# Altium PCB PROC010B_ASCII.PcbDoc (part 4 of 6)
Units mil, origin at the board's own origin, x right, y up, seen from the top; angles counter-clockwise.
Board outline 3180 x 2565 mil, 6 copper layers (TOP, L2, L3, L4, L5, BOTTOM), stack 55.54 mil thick; 362 components, 264 nets, 1248 pads, 1144 vias.
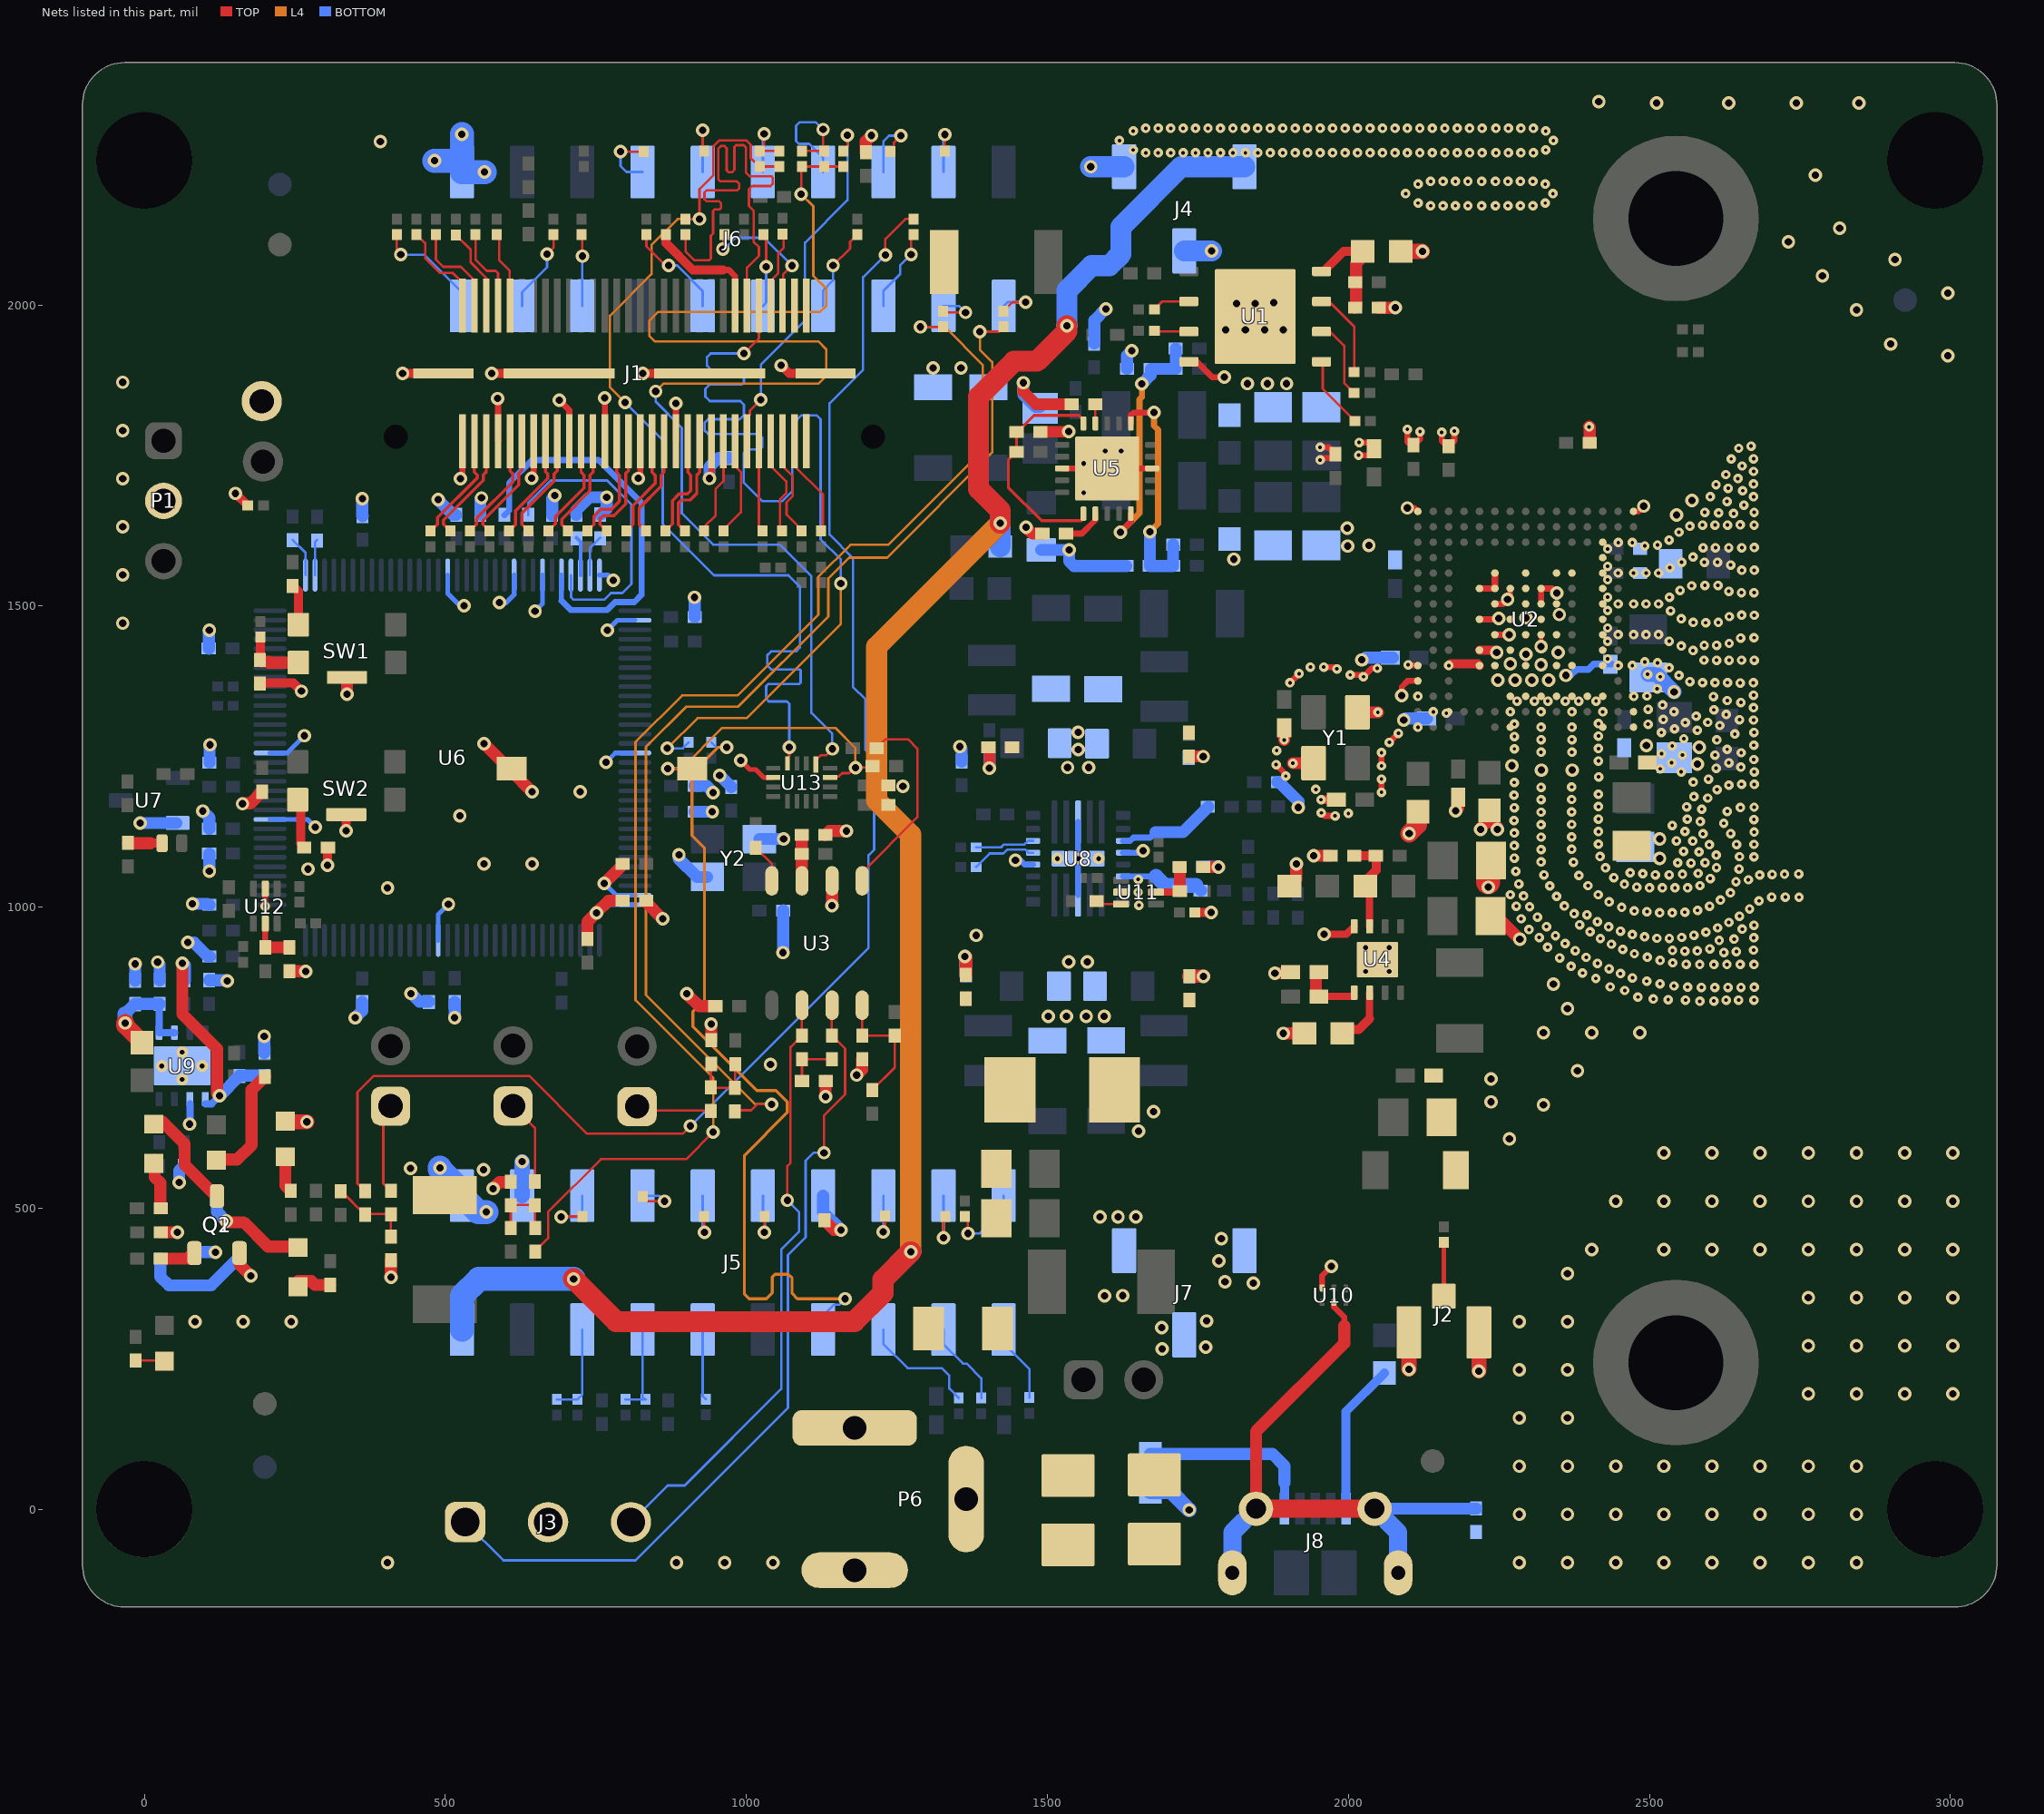
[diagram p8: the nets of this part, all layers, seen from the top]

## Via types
v1: diameter 22.4, hole 12.2, TOP to BOTTOM, tented both sides, 621 vias
v2: diameter 15.74, hole 5.9, TOP to L2, tented top, 508 vias
v3: diameter 19.68, hole 7.87, TOP to BOTTOM, tented top, 7 vias
v4: diameter 19.68, hole 7.87, TOP to BOTTOM, 4 vias
v5: diameter 19.68, hole 7.87, TOP to BOTTOM, tented both sides, 3 vias
v6: diameter 19.68, hole 7.87, TOP to BOTTOM, tented bottom, 1 vias

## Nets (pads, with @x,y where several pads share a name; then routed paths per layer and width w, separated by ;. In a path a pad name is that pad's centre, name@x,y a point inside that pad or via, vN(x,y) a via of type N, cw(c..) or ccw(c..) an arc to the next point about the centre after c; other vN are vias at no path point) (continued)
GND: C1.1 C2.1 C3.2 C4.2 C5.2 C6.2 C7.2 C8.2 C9.2 C10.2 C11.1 C12.2 C13.2 C14.2 C15.1 C16.1 C17.2 C19.2 C20.1 C21.2 C22.2 C23.2 C24.1 C25.2 C26.2 C27.2 C29.1 C30.1 C31.1 C32.1 C33.1 C34.1 C35.1 C36.1 C37.1 C38.1 C39.2 C40.1 C41.1 C42.1 C43.1 C44.1 C45.2 C47.2 C48.2 C49.1 C50.1 C51.2 C52.2 C53.2 C54.1 C55.1 C56.2 C57.2 C58.2 C59.1 C60.1 C61.1 C62.1 C63.1 C64.1 C65.2 C66.1 C67.1 C68.1 C69.1 C70.1 C71.1 C72.1 C73.1 C74.1 C75.1 C76.1 C77.1 C79.1 C80.1 C81.1 C82.1 C83.2 C84.1 C85.2 C86.1 C87.1 C88.1 C89.1 C90.1 C91.1 D3.2 DS2.2 J1.18 J1.24 J1.30 J1.36 J1.42 J1.48 J1.54 J1.60 J1.MP1 J1.MP2 J1.MP3 J1.MP4 J2.2 J2.3 J3.2 J4.1 J4.2 J5.4 J6.2 J7.1 J7.2 P1.2 P6.2 P6.3 Q1.2 Q2.2 R13.1 R47.2 R73.1 R79.1 R81.1 R83.1 R86.2 R88.1 R96.1 R110.1 R114.1 R119.1 R121.1 R123.2 R126.2 R132.1 R138.1 R139.1 R153.1 R157.1 R158.1 R174.1 R175.1 R181.2 R194.1 R195.2 R196.1 S1.1 SW1.5 SW2.5 TP1.1 U1.4 U1.9 U2.A1 U2.A3 U2.A5 U2.A7 U2.A9 U2.A15 U2.B1 U2.B3 U2.B5 U2.B7 U2.B9 U2.B13 U2.B14 U2.C1 U2.C3 U2.C4 U2.C5 U2.C6 U2.C7 U2.C8 U2.C9 U2.C15 U2.D15 U2.E1 U2.E2 U2.E3 U2.E5 U2.E6 U2.E8 U2.E10 U2.E11 U2.E13 U2.E15 U2.F3 U2.F9 U2.F11 U2.G1 U2.G2 U2.G3 U2.G6 U2.G7 U2.G8 U2.G10 U2.H3 U2.H7 U2.H9 U2.H11 U2.J1 U2.J2 U2.J3 U2.J6 U2.J7 U2.J8 U2.J10 U2.K3 U2.K7 U2.K8 U2.K9 U2.K10 U2.K11 U2.L1 U2.L2 U2.L3 U2.L5 U2.L6 U2.L8 U2.L10 U2.M3 U2.N1 U2.N2 U2.N3 U2.R1 U2.R15 U3.2 U4.4 U4.9 U5.3 U5.13 U5.21@1599.35,1728.32 U6.10 U6.17 U6.48 U6.55 U6.58 U6.64 U6.66 U6.80 U6.114 U7.2 U8.4 U8.11 U8.17 U8.24 U8.27 U9.6 U9.9@62.83,736.32 U10.3 U11.2 U12.2 U13.6 Y1.2 Y1.4 Y2.2 Y2.4 | length 6887.4
  TOP w7: U2.J7@2318.89,1503.49 U2.J7@2320.14,1503.49 U2.J7@2320.61,1503.49 ; U2.G7@2320.14,1452.31 U2.G7@2320.14,1452.31 v1@2320.14,1432.71
  TOP w7.8: v1(990.51,1243.73) 1005.75,1228.49 1015.79,1228.49 1029.2,1215.08 U13.6@1044.61,1215.08
  TOP w9: v1(2264.45,1510.8) 2268.96,1515.31 U2.K9@2268.96,1529.08
  TOP w9.45: U5.3@1524.55,1728.32 U5.13@1674.15,1728.32
  TOP w10: v2(200.81,1001.56) U12.2@200.82,1030.67 ; v1(524.98,1711.53) 528.62,1715.17 J1.60@528.62,1773.27 ; v1(587,1844.5) 587.67,1844.5 J1.54@587.67,1773.27 ; v1(643.53,1711.97) 646.73,1715.17 J1.48@646.73,1773.27 ; v1(689.11,1841.85) 705.78,1825.18 J1.42@705.78,1773.46 J1.42@705.78,1773.27 ; J1.36@764.84,1773.27 v1(764.84,1845.5) ; v1(820.61,1711.89) 823.89,1715.17 J1.30@823.89,1773.27 ; J1.24@882.95,1773.46 v1(882.95,1836.43) ; v1(938.67,1711.84) 942,1715.17 J1.18@942,1773.27 ; U1.4@1734.99,1905.68 1748.12,1905.68 1773.8,1880 v1(1794,1880) ; v2(1880,1236.5) 1896,1220.5 v2(1896,1217.5) ; v2(1903,1372.5) v2(1918,1387.5) ; v2(1953,1742.5) 1956,1745.5 1971.95,1745.5 C7.2@1978.55,1752.1 1967.15,1763.5 v2(1953,1763.5) ; v2(1955,1156.5) 1960,1151.5 v2(1978,1151.5) ; U10.3@1956.31,367.31 1956.31,387.81 v1(1972,403.5) ; v2(1959,1398.5) 1978,1398.5 v2(1981,1395.5) ; v2(2003,1385.5) 2022,1385.5 v2(2025,1382.5) 2039,1396.5 v2(2048,1396.5) ; v2(2017,1750.5) 2035.8,1750.5 C6.2@2042.4,1757.1 ; v2(2018,1771.5) 2031.04,1771.5 2042.55,1759.99 C6.2@2042.55,1757.1 ; v2(2055,1190.5) v2(2055,1212.5) ; v2(2055,1234.5) v2(2055,1256.5) ; v2(2068,1273.5) v2(2083,1288.5) ; v1(2088.81,1351.12) 2088.81,1366.05 2098.3,1375.54 U2.D15@2115.42,1375.54 ; v1(2098,1662.8) 2109.65,1662.8 U2.R15@2115.42,1657.03 ; v2(2098,1793.5) 2098,1772.68 2105.35,1765.33 2107.83,1765.33 2119,1776.5 v2(2119,1789.5) ; v2(2099.17,1402.27) 2100.32,1401.13 U2.E15@2115.42,1401.13 ; v2(2155,1788.5) 2155,1774.5 2164.8,1764.7 2166.55,1764.7 2176,1774.15 v2(2176,1790.5) ; U2.H11@2217.78,1477.9 2248.55,1477.9 v1(2250.05,1479.4) ; U2.G10@2243.37,1452.31 v1@2266.94,1452.31 ; U2.J10@2243.37,1503.49 2257.14,1503.49 v1(2264.45,1510.8) ; U2.J7@2320.14,1503.49 U2.K7@2320.14,1529.08 2338.42,1529.08 v1(2346,1521.5) ; U2.R1@2473.68,1657.03 2481.68,1657.03 v1(2490.55,1665.9)
  TOP w11: U2.K11@2217.78,1529.08 U2.K10@2243.37,1529.08 U2.L10@2243.37,1554.67
  TOP w12: v1(1959.84,954.74) 1996.49,954.74 U4.4@2009.79,968.04
  TOP w15: v1(151.5,1687) C8.2@171.7,1666.75 C8.2@171.7,1666.75 ; R73.1@192.05,1372.02 247.48,1372.02 v1(261,1358.5) ; v1(304.25,1069.5) R79.1@304.25,1098.84 ; v1(335.35,1126.5) SW2.5@335.35,1153.66 ; v1(429,1886.26) J1.MP4@496.53,1886.26 J1.MP4@496.73,1886.26 ; v1(576.76,1886.26) J1.MP3@689.05,1886.26 J1.MP3@689.25,1886.26 ; v1(828,1886.26) J1.MP2@939.05,1886.26 J1.MP2@939.25,1886.26 ; v1(1058,1899.5) 1071.24,1886.26 J1.MP1@1131.57,1886.26 J1.MP1@1131.77,1886.26 ; R181.2@1745.21,991.17 1771.83,991.17 v1(1772,991) ; v2(1954.5,1178.34) C15.1@1979.85,1178.34 ; v2(2166.6,1401.13) 2169.17,1403.7 2215.21,1403.7 U2.E11@2217.78,1401.13 ; U2.F11@2217.78,1426.72 2242.33,1426.72 v1(2246.35,1422.7)
  TOP w19: v1(1460,1870.8) 1460,1855.92 1481,1834.93 C44.1@1540.29,1834.93 ; R47.2@1488.22,1788.74 1489.05,1789.57 v1(1535.6,1789.57)
  TOP w19.6: R88.1@941.42,778.84 v1(941.42,805.97)
  TOP w19.68: v1(1464.51,1630.67) 1474.92,1620.25 C29.1@1491.66,1620.25
  TOP w20: R110.1@26.62,459.77 R110.1@27.4,459.77 v1(55,459.77) ; Q1.2@157.98,427.47 157.98,406.52 v1(177,387.5) ; v1(163,1171.5) 163,1172.5 176.25,1172.5 C11.1@195.7,1191.95 ; C85.2@242.2,893.35 v1(268.05,893.35) ; v1(336.65,1353.5) SW1.5@336.65,1381.42 ; v1(409.52,385.5) R114.1@409.52,413.47 R114.1@409.52,414.25 ; v1(564,1271.5) 605.5,1230 S1.1@610,1230 610,1225.5 v1(644,1191.5) ; v1(579.2,532.5) 589.85,543.15 R96.1@608.78,543.15 ; C71.1@833.3,1010.5 833.3,1008.2 v1(861,980.5) ; v1(901,856) 921.55,835.45 C20.1@948.59,835.45 ; C16.1@1131.38,1119.67 1137.98,1126.27 v1(1166.49,1126.27) ; v1@1131.74,684.9 C24.1@1131.74,711.14 ; v1(1142.37,1002.36) U3.2@1142.37,1043.6 ; v1(1183.27,720.91) 1192.37,730.01 R86.2@1192.37,747.12 ; R13.1@1198.4,2252.95 R13.1@1198.4,2253.73 1198.4,2271.9 v1(1208,2281.5) ; C84.1@1758.65,1066.5 C84.1@1759.03,1066.5 v1(1784,1066.5) ; v1(1877.95,890.07) 1901.78,890.07 R83.1@1903.73,892.02 R83.1@1908.45,892.02 ; v1(1892,790.27) C22.2@1926.97,790.27 ; v2(1893.4,1277.69) C9.2@1893.4,1297.59 ; C91.1@1902.01,1034.87 1913.5,1046.36 v1(1913.5,1071.72) ; v2(1908,1238.82) Y1.4@1942.3,1238.82 ; v1@1942.56,1085.17 R81.1@1970.2,1085.17 ; Y1.2@2015.14,1323.46 v2(2049,1323.46) ; C2.1@2050.08,1995.26 C2.1@2050.47,1995.26 v1(2078,1995.26) ; v1(2178.28,1160.07) 2182.55,1164.34 C12.2@2182.55,1182.18 ; v1(2219.55,1128.8) 2219.55,1131.18 2234.45,1146.08 C13.2@2234.45,1160.4 ; C13.2@2234.45,1143.7 2236.42,1143.7 2247.55,1132.57 v1(2247.55,1128.8) ; C19.2@2236.23,984.99 2246.34,984.99 v1(2284.77,946.56) ; v2(2400,1797.5) 2400.85,1796.65 C3.2@2400.85,1770.8
  TOP w25: DS2.2@234.35,643.37 v1(270,643.37) ; C1.1@2086.97,2088.99 v1(2123,2088.99) ; v1(2100.64,232.5) J2.2@2100.64,293.72 ; v1(2216.78,229.5) J2.3@2216.78,293.72
  TOP w30: v1(2101,1122.3) 2115.45,1136.75 C14.2@2115.45,1158.3
  TOP w40: v1@2232.21,1041.59 2232.21,1072.78 C17.2@2236.81,1077.38
  BOTTOM w8: U6.10@208.64,1145.68 270.82,1145.68 v1(284,1132.5) ; U6.17@208.64,1255.91 237.41,1255.91 v1(266,1284.5) ; U6.114@488.17,944.89 488.17,987.67 v1(505,1004.5) ; U6.48@503.92,1551.19 503.92,1520.59 524.01,1500.5 v1(531,1500.5) ; v1(590,1505.5) 601,1505.5 614.15,1518.65 U6.55@614.15,1551.19 ; v1(649,1491.5) 661.4,1503.9 U6.58@661.4,1551.19 ; U6.64@755.88,1551.19 770.31,1551.19 v1(779,1542.5) ; v1(766.88,1240.5) 782.29,1255.91 U6.80@814.94,1255.91 ; v1(769,1459.5) 785.89,1476.39 U6.66@814.94,1476.39
  BOTTOM w9.84: U8.24@1551,1019.87 v3(1551,1080.5) U8.11@1551,1141.13
  BOTTOM w10: v1(1447,1077.79) 1455.09,1077.79 1462.22,1070.66 U8.4@1476.2,1070.65 ; U8.17@1625.81,1090.34 1655.84,1090.34 v1(1659,1093.5)
  BOTTOM w11.4: v1@2368.75,1384.8 2378.65,1394.7 2379.58,1394.7 2379.88,1394.4 2397.62,1394.4 2397.92,1394.7 2398.77,1394.7 2407.67,1403.6 C51.2@2437.15,1403.6
  BOTTOM w12: v1(75,639.5) 75.63,639.5 U9.6@75.63,673.32 ; v1(2361.25,1384.8) v1@2368.75,1384.8
  BOTTOM w20: C80.1@-15.4,877.8 C80.1@-15.4,878.18 v1(-15.4,905.5) ; v1@-7,1139.69 U7.2@53.36,1139.69 ; v1(22,908.5) 25.62,904.88 C79.1@25.62,878.53 C79.1@25.62,878.15 ; v1(58,542.5) 58,562.49 R158.1@65.68,570.16 R158.1@65.68,570.95 ; v1(72.17,941.23) 82.27,941.23 105.76,917.74 R153.1@107.96,917.74 R153.1@108.75,917.74 ; v1(80,1005.5) 105,1005.5 106.94,1003.56 C69.1@107.96,1003.56 C69.1@108.35,1003.56 ; Q2.2@83.22,426.89 v1(118,426.89) ; v1(97,1159.5) 107.89,1148.61 C66.1@107.89,1130.1 ; C50.1@107.35,1429.4 107.35,1459.5 v1(108,1459.5) ; C77.1@107.82,878.45 134,878.45 134,877.5 v1(138,877.5) ; v1(107.95,1059.5) C67.1@107.95,1088.8 ; C61.1@108.35,1240.06 108.35,1269.5 v1(109,1269.5) ; R157.1@199.2,757.75 R157.1@199.2,758.53 v1(199.2,785.5) ; v1(350.22,815.97) 361.92,827.67 C76.1@361.92,842.16 ; v1(362,1678.5) 361.73,1678.23 361.73,1649.94 C43.1@362.52,1649.15 ; v1(443,856.5) 456.65,842.85 C75.1@472.68,842.85 ; v1(488,1676.5) 513.35,1651.15 C42.1@518.22,1651.15 ; v1(515.51,816.23) 515.51,842.38 C74.1@515.6,842.47 ; C41.1@558.3,1651.15 C41.1@558.3,1651.53 558.3,1677.8 v1(560,1679.5) ; R194.1@677.52,1650.75 R194.1@677.52,1651.53 677.52,1679.02 v1(682,1683.5) ; R126.2@717.68,1651.05 R126.2@717.68,1651.84 717.68,1659.18 739,1680.5 v1(768,1680.5) 768,1661.77 R123.2@757.28,1651.05 ; v1(887.92,1086.69) 887.92,1080 917.92,1050 Y2.4@935,1050 ; C49.1@914.03,1481.9 v1(914.03,1514.4) ; C64.1@914.34,1158.3 v1(943.5,1158.3) ; C62.1@914.34,1201.5 933.5,1201.5 v1(945,1190) ; v1(938.67,1711.84) 938.67,1730.6 953.66,1745.6 R196.1@971,1745.6 ; v1(955.62,1218.91) C70.1@975,1199.53 ; Y2.2@1021.61,1112.99 v1(1061.88,1112.99) ; v1(1060.98,924.46) C63.1@1060.98,994.36 ; v1(1354.39,1266.55) 1357.78,1263.16 R138.1@1357.78,1241.65 ; v1(1460,1870.8) 1460,1851 1480.6,1830.4 C32.1@1487.95,1830.4 ; C40.1@1489.95,1593.05 v1(1536.06,1593.05) 1536.06,1574.71 1544.25,1566.52 R132.1@1631.1,1566.52 ; R119.1@1577.96,1935.82 1577.96,1974.36 v1(1597.04,1993.44) ; R121.1@1632.33,1893.62 1632.33,1916.07 v1(1640.06,1923.79) ; C68.1@1759.14,1067 1783.5,1067 v1(1784,1066.5) ; R139.1@1882.25,1207.54 R139.1@1883.03,1207.54 1884.96,1207.54 1917,1175.5 v1(1917,1165.5) ; v1(2022,1410.5) 2025,1410.5 2028.5,1414 C53.2@2069.73,1414 C53.2@2074.05,1414 ; v1(2092,1310.72) 2094.57,1313.3 C56.2@2130.21,1313.3
  BOTTOM w25: J5.4@627.5,520.72 v1(627.5,577.18) ; R175.1@1671,29 1705.5,29 v1(1735.5,-1) ; C52.2@2498.15,1386 2512.5,1386 v1(2541,1357.5)
  BOTTOM w35: v1(1572.02,2229.48) J4.1@1627.5,2229.48 ; J4.2@1727.5,2089.52 v1(1773,2089.52)
  BOTTOM w40: v1(482,2239.5) J6.2@527.5,2239.5 ; v1(527.5,2283.5) J6.2@527.5,2239.5 ; v1(565,2220.72) J6.2@527.5,2220.72 J6.2@527.5,2239.5
  other v1: 404,-88.5 884,-88.5 964,-88.5 1044,-88.5 2284,-88.5 2364,-88.5 2444,-88.5 2524,-88.5 2604,-88.5 2684,-88.5 2764,-88.5 2844,-88.5 2284,-8.5 2364,-8.5 2444,-8.5 2524,-8.5 2604,-8.5 2684,-8.5 2764,-8.5 2844,-8.5 2284,71.5 2364,71.5 2444,71.5 2524,71.5 2604,71.5 2684,71.5 2764,71.5 2844,71.5 2284,151.5 2364,151.5 2764,191.5 2844,191.5 2924,191.5 3004,191.5 2284,231.5 2364,231.5 1690.45,265.99 1762.97,269.04 2764,271.5 2844,271.5 2924,271.5 3004,271.5 1689.78,301.36 84,311.5 164,311.5 244,311.5 2284,311.5 2364,311.5 1764.66,312.64 2764,351.5 2844,351.5 2924,351.5 3004,351.5 1595.23,354.53 1625.27,354.72 2364,391.5 2404,431.5 2524,431.5 2604,431.5 2684,431.5 2764,431.5 2844,431.5 2924,431.5 3004,431.5 1587.28,485.48 1617.32,485.48 1647.14,485.48 2444,511.5 2524,511.5 2604,511.5 2684,511.5 2764,511.5 2844,511.5 2924,511.5 3004,511.5 2524,591.5 2604,591.5 2684,591.5 2764,591.5 2844,591.5 2924,591.5 3004,591.5 2267.43,614.93 1651.58,628.04 1676.13,660.27 2324,671.5 2237,676.5 1131.59,684.9 2237,714.5 2380.57,728.07 1040,738.5 2324,791.5 2404,791.5 2484,791.5 1501.55,818.8 1531.55,818.8 1564.55,818.8 1594.55,818.8 2364,831.5 2340.65,871.84 1535.55,908.8 1566.55,908.8 1382,953 404,1031.5 2232.49,1033 272,1063 564,1071.5 644,1071.5 2517,1081 1942.36,1085.17 2517,1113 -7,1139.5 524,1151.5 724,1191.5 1260.01,1200.67 2320.4,1227.39 2372.1,1227.4 1533.55,1231.8 1568.55,1231.8 2271.6,1234.9 2580,1237.5 1551.24,1261.57 2583,1265.5 2495,1268.5 1551.02,1290.27 2248.35,1377 2276.75,1377 2304.75,1377 2332.75,1376.8 2320.15,1402.7 2268.95,1404.2 2295.05,1419.7 2348.75,1422.9 2320.15,1432.7 2266.95,1452.3 -36,1471.5 2295.05,1480.4 2350.45,1485.8 -36,1551.5 1810.01,1577.67 1999,1599.5 2034,1600.5 1998,1629.5 -36,1631.5 2545,1651.2 2571,1675.5 -36,1711.5 -36,1791.5 1832.44,1869.27 1865.44,1869.27 1897.44,1869.27 -36,1871.5 1356.45,1895.35 1310.2,1895.5 2996,1915.5 2900.57,1934.93 1796,1958.5 1829,1958.5 1861,1958.5 1892,1958.5 2844,1991.5 1814,2002.5 1845.2,2002.55 1876,2003.5 2996,2019.5 2787.43,2048.07 2908,2075.5 2730.86,2104.64 2816,2127.5 2776,2215.5 392,2271.5 2512,2335.5 2632,2335.5 2744,2335.5 2848,2335.5 2416,2337.5
  other v2: 2583.7,843.5 2607,843.9 2560,845.4 2531.2,846.2 2627.6,845.6 2648.2,845.6 2673.8,845.6 2506.5,847.4 2481,850.5 2459,861.5 2608.6,866.4 2630.6,866.5 2563.5,867.1 2586.4,866.6 2652.2,866.6 2674.1,866.9 2435,867.5 2540.7,869 2517.6,872.5 2495.5,876.9 2411,881.5 2472,882.5 2389,890.5 2452,889.5 2433,897.5 2370,901.5 2673.9,904.5 2561.2,905.1 2583.6,904.7 2607.1,904.7 2628.8,904.7 2650.8,904.8 2414,906.5 2538.7,907.4 2517.9,911.5 2351,915.5 2395,916.5 2496.6,916.7 2475.1,922.5 2623.8,924.7 2644.4,926.2 2559,926.8 2579.6,927.3 2377,927.5 2538.4,928 2673,928.5 2455.7,929.7 2600.4,930.7 2331,933.5 2436.9,938.3 2360,939.5 2616,944.5 2640.7,946.8 2418.6,947.8 2512.5,948.1 2533.1,947.9 2673.5,949.1 2317,949.5 2492,950.5 2553.7,949.6 2344,952.5 2574,953.3 2471.7,954.3 2594,958.3 2401.3,959.1 2451.8,959.9 2300,962.5 2654.2,963.3 2613.3,965.5 2432.4,967.1 2329,967.5 2384.1,970.5 2673.8,969.7 2631.9,974.5 2413.7,975.8 2287,980.5 2314,983.5 2649.7,984.9 2396.4,987.1 2375.1,989.1 2517,990.5 2538,990.5 2496,992.5 2559,991.5 2475,993.5 2580,994.5 2666.5,996.9 2301,1000.5 2454,999.5 2279,1001.5 2358.8,1001.8 2600,1001.5 1652,1003 2433,1008.5 2682.2,1010.3 2618,1011.5 2703.3,1016.4 2725.8,1016.4 2748.6,1016.3 2291,1018.5 2345.8,1017.8 2269,1020.5 2415,1020.5 2634.7,1023.7 1650.75,1024.75 2500,1032 2521.5,1032 2542.5,1032 2563.5,1032 2479,1033 2334.5,1035.1 2398,1035.5 2584,1035.5 2283,1038.5 2458.5,1038 2643.9,1042.2 2664.3,1045.3 1651,1046 2601,1047.5 2441,1049 2383,1052.5 2683.3,1053.3 2325,1053.5 2510,1053.5 2533,1053.5 2555,1054.5 2703.9,1054.2 2724.5,1054.5 2748.1,1055 2489,1055.5 2580.9,1055.9 2468,1057 2278,1059.5 2649,1063.2 2427,1065 2611.5,1065.5 2569.1,1072.9 2374,1074.5 2547,1073.6 2592.5,1073.7 2320.1,1074.8 2275.6,1081.3 2673.9,1083.4 2418,1084 2649.8,1083.8 2611.1,1086.1 2582.4,1091.7 2556.9,1092.6 2320.1,1095.5 2370.9,1095.9 2275.7,1102.1 2415.5,1104.5 2599.5,1103.5 2644.9,1103.9 2673.8,1104.1 2545,1110 2572.1,1109.6 2320.1,1116.2 2370.9,1116.6 2589,1121.5 2634.9,1121.9 2275.6,1123.1 2415.5,1125.35 2674,1124.7 2559.1,1125.6 2538,1135.5 2320.1,1136.9 2370.9,1137.3 2623.5,1139.1 2584.5,1142 2275.3,1143.7 2673.6,1145.3 2415.5,1146.05 2563,1145.9 2000,1155.5 2320.1,1157.6 2370.9,1158 2629.3,1158.9 2587,1162.5 2275.5,1165 2651.2,1165.2 2562,1166.5 2674,1165.9 2415.5,1166.75 2320.1,1178.3 2370.9,1178.7 2597,1181 2574,1183.5 2275.3,1185.9 2415.5,1187.4 2612.5,1195 1946,1195.5 2320.1,1199 2370.9,1199.4 2632,1202.5 2653,1204 2674.1,1203.8 2275.7,1207 2573,1207.5 2598,1212.5 2415.7,1216.1 2553,1224.5 2674.1,1224.4 2518,1229.5 2611,1230.5 2652.1,1232.3 2537,1239.5 2632,1239.5 2415.45,1242.6 2673.5,1245 2555,1252.5 2609,1252.5 2520,1254.5 2652.6,1256.3 2320.14,1257.37 2371.32,1257.37 1881,1260 2629.2,1261.9 2275.85,1262.7 2415.45,1263.3 2538,1267.5 2673.5,1268.7 2320.14,1278.07 2371.32,1278.07 2612,1277.5 2557.2,1279.4 2275.85,1283.35 2415.45,1283.95 2642,1287.5 2519.9,1289.8 2673.7,1290 2579.7,1293.6 2541.8,1295.9 2115.42,1298.77 2320.14,1298.77 2371.32,1298.77 2617,1301.5 2275.85,1304 2498,1303.5 2415.45,1304.6 2559.6,1306.4 2596.9,1306.8 2649.7,1311.1 2673,1310.6 2523,1311.5 2577.7,1317 2627.7,1319.9 2162.8,1321.9 2141.01,1324.36 2268.96,1324.36 2320.14,1324.36 2371.32,1324.36 2422.5,1324.36 2540.7,1324.5 2498,1328.5 2607,1327.5 2673.2,1331.2 2522,1335.5 2652.1,1339.8 2280.15,1341.9 2309.05,1341.9 2331.35,1341.9 2360.25,1341.9 2382.55,1341.9 2411.45,1341.9 2629.3,1343 2115.42,1349.95 2474.1,1349.95 2496,1350.5 2606.5,1349.6 2673,1351.8 2513,1362.5 2650.7,1372.28 2672.8,1372.48 2588.3,1372.68 2609,1372.68 2629.7,1372.68 2567.2,1374.48 2518,1382.5 2549,1384.8 2497,1386.5 2532.7,1397.48 1937,1398.5 2448.09,1401.13 2471.7,1401.13 2513.5,1405.68 2492.4,1407.28 2590.8,1410 2611.7,1409.9 2632.5,1409.9 2653.2,1410 2674.1,1409.9 2430.65,1412.3 2572.4,1426 2553,1433.5 2591.1,1434.8 2611.7,1434.8 2632.6,1437.9 2430.65,1441.3 2533,1441.5 2651.5,1446.9 2673.7,1447.3 2448.09,1452.31 2473.68,1452.31 2494.38,1452.31 2515.08,1452.31 2430.65,1463.5 2593.7,1472.2 2573,1472.7 2614.5,1472.8 2552.8,1478.9 2632.8,1482.4 2653.3,1484.7 2674.1,1484.6 2430.65,1492.5 2535.1,1492.1 2448.09,1503.49 2473.68,1503.49 2494.38,1503.49 2515.08,1503.49 2533.2,1514.4 2430.65,1514.7 2652.9,1522 2673.9,1522.2 2632.1,1524.3 2550.9,1526 2570.3,1533.6 2592.3,1534.3 2613.8,1534.1 2430.65,1543.7 2448.09,1554.67 2473.68,1554.67 2494.38,1554.67 2515.08,1554.67 2653.6,1559.4 2674.2,1559.4 2534,1563.5 2430.65,1565.9 2634.9,1568.2 2613.2,1572.5 2553.5,1572.6 2591.4,1572.6 2572.6,1581.5 2430.65,1594.9 2589.3,1596.8 2609.9,1596.8 2631.8,1596.7 2653.6,1596.8 2674.2,1597.1 2492.4,1599.7 2513.5,1601.3 2448.4,1605.4 2471.7,1605.4 2532.7,1609.5 2549,1622.5 2567.2,1632.5 2588.3,1634.3 2609,1634.3 2629.7,1634.3 2674,1634.5 2650.7,1634.7 2615,1654.5 2640,1653.5 2592,1655.5 2674,1655.5 2657,1667.5 2629,1673.5 2601.2,1681.5 2673,1681.5 2655,1691.5 2631,1695.5 2610.7,1701.5 2673,1702.5 2647,1711.5 2627,1718.2 2673,1723.5 2654,1732.5 2635.9,1744.2 2673,1744.5 2648.4,1761.9 2669,1765.5 2136.47,2164.6 2157.17,2164.6 2177.87,2164.6 2198.57,2164.6 2221.43,2164.6 2244.3,2164.6 2265,2164.6 2285.7,2164.6 2306.4,2164.6 2115.77,2169.2 2327,2169.2 2095.07,2184.9 2339.8,2184.9 2115.77,2200.6 2327,2200.6 2136.47,2205.2 2157.17,2205.2 2177.87,2205.2 2198.57,2205.2 2221.43,2205.2 2244.3,2205.2 2265,2205.2 2285.7,2205.2 2306.4,2205.2 1663.3,2252.7 1684,2252.7 1704.7,2252.7 1725.4,2252.7 1746.1,2252.7 1766.8,2252.7 1787.5,2252.7 1808.2,2252.7 1828.9,2252.7 1849.6,2252.7 1870.3,2252.7 1891,2252.7 1911.7,2252.7 1932.4,2252.7 1953.1,2252.7 1973.8,2252.7 1994.5,2252.7 2015.2,2252.7 2035.9,2252.7 2056.6,2252.7 2077.3,2252.7 2098,2252.7 2118.7,2252.7 2139.4,2252.7 2160.1,2252.7 2180.8,2252.7 2201.5,2252.7 2222.2,2252.7 2245.1,2252.7 2265.8,2252.7 2286.5,2252.7 2307.2,2252.7 1642.7,2257.3 2327.8,2257.3 1619.7,2273 2340.6,2273 1642.7,2288.7 2327.8,2288.7 1663.3,2293.3 1684,2293.3 1704.7,2293.3 1725.4,2293.3 1746.1,2293.3 1766.8,2293.3 1787.5,2293.3 1808.2,2293.3 1828.9,2293.3 1849.6,2293.3 1870.3,2293.3 1891,2293.3 1911.7,2293.3 1932.4,2293.3 1953.1,2293.3 1973.8,2293.3 1994.5,2293.3 2015.2,2293.3 2035.9,2293.3 2056.6,2293.3 2077.3,2293.3 2098,2293.3 2118.7,2293.3 2139.4,2293.3 2160.1,2293.3 2180.8,2293.3 2201.5,2293.3 2222.2,2293.3 2245.1,2293.3 2265.8,2293.3 2286.5,2293.3 2307.2,2293.3
  other v3: 62.83,713.68 29,736 96,736 62.83,758.96 1516.75,1080.5 1585.26,1080.5
  other v4: 2028.49,893.24 2067.86,893.24 2028.49,932.61 2067.86,932.61
  other v5: 1560.41,1688.18 1560.41,1736.5 1622.39,1757.57
  other v6: 1596.03,1757.57
HD_LVDS_VALID_N: J1.22 R60.1 | length 176
  TOP w5.2: R60.1@865.55,1624.71 877,1636.16 877,1675.03 888.17,1686.2 902.17,1686.2 907.37,1691.4 907.37,1717.31 902.63,1722.05 J1.22@902.63,1773.27
HD_LVDS_VALID_P: J1.20 R61.1 | length 175.7
  TOP w5.2: R61.1@897.75,1624.71 887.2,1635.26 887.2,1670.8 892.4,1676 906.4,1676 917.57,1687.17 917.57,1717.31 922.32,1722.06 J1.20@922.32,1773.27
HD_LVDSCSI0_N: J1.58 R48.1 | length 182.6
  TOP w5.2: R48.1@475.61,1624.71 486.83,1635.93 486.83,1646.76 553,1712.93 553,1717.35 548.3,1722.05 J1.58@548.3,1773.27
HD_LVDSCSI0_P: J1.56 R49.1 | length 182.6
  TOP w5.2: R49.1@508.25,1624.71 497.03,1635.93 497.03,1642.53 563.2,1708.7 563.2,1717.88 567.99,1722.67 J1.56@567.99,1773.27
HD_LVDSCSI1_N: J1.52 R50.1 | length 179.8
  TOP w5.2: R50.1@540.75,1624.71 551.9,1635.86 551.9,1645.84 611.8,1705.74 611.8,1719.71 607.36,1724.15 J1.52@607.36,1773.27
HD_LVDSCSI1_P: J1.50 R51.1 | length 180.1
  TOP w5.2: R51.1@573.25,1624.71 562.1,1635.86 562.1,1641.61 622,1701.51 622,1720.51 627.04,1725.55 J1.50@627.04,1773.27
HD_LVDSCSI2_N: J1.40 R54.1 | length 174.9
  TOP w5.2: R54.1@671.35,1624.71 683,1636.37 683,1648.5 730.21,1695.71 730.21,1717.31 725.47,1722.05 J1.40@725.47,1773.27
HD_LVDSCSI2_P: J1.38 R55.1 | length 174.5
  TOP w5.2: R55.1@703.85,1624.71 693.2,1635.36 693.2,1644.27 740.41,1691.48 740.41,1717.31 745.15,1722.05 J1.38@745.15,1773.27
HD_LVDSCSI3_N: J1.34 R56.1 | length 183.2
  TOP w5.2: R56.1@735.75,1624.71 746.8,1635.76 746.8,1649.32 757.98,1660.5 776,1660.5 789.26,1673.76 789.26,1717.31 784.52,1722.05 J1.34@784.52,1773.27
HD_LVDSCSI3_P: J1.32 R57.1 | length 183.2
  TOP w5.2: R57.1@768.05,1624.71 757,1635.76 757,1645.09 762.21,1650.3 780.23,1650.3 799.46,1669.53 799.46,1717.31 799.81,1717.66 799.81,1720.51 804.21,1724.91 J1.32@804.21,1773.27
HD_LVDSCSI_CLK_N: J1.46 R52.1 | length 176.9
  TOP w5.2: R52.1@605.75,1624.71 616.9,1635.86 616.9,1658.4 670.32,1711.82 670.32,1719.18 666.41,1723.09 J1.46@666.41,1773.27
HD_LVDSCSI_CLK_P: J1.44 R53.1 | length 177.6
  TOP w5.2: R53.1@638.25,1624.71 627.1,1635.86 627.1,1654.17 680.52,1707.59 680.52,1719.01 686.1,1724.59 J1.44@686.1,1773.27
HD_LVDSCSI_FRCLK_N: J1.28 R58.1 | length 170.3
  TOP w5.2: R58.1@800.55,1624.71 811.7,1635.86 811.7,1666.63 848.32,1703.25 848.32,1717.31 843.58,1722.05 J1.28@843.58,1773.27
HD_LVDSCSI_FRCLK_P: J1.26 R59.1 | length 170.3
  TOP w5.2: R59.1@833.05,1624.71 821.9,1635.86 821.9,1662.4 858.52,1699.02 858.52,1717.31 863.26,1722.05 J1.26@863.26,1773.27
LDO_01_EN: R83.2 R84.1 U4.5 | length 104.6
  TOP w12: R84.1@1946.93,851.9 U4.5@2009.79,851.9
  TOP w20: R83.2@1946.25,892.02 1946.25,851.22 R84.1@1946.93,851.9
LDO_02_EN: R46.2 R47.1 U5.6 U5.20 | length 386.1
  TOP w5: U5.6@1559.98,1653.52 1559.98,1645.37 1556.25,1641.64 1490.41,1641.64 1435.14,1696.91 1435.14,1742.4 R46.2@1448.85,1756.11 1448.85,1787.67 1477.9,1816.72 1552.28,1816.72 1559.98,1809.02 U5.20@1559.98,1803.12
MCU_3V3: J4.3 J5.1 R130.1 | length 3152.4
  TOP w35: v1(713,382.5) 784,311.5 1179.5,311.5 1226.86,358.87 1226.86,381.36 v1(1273,427.5) ; v1(1421.81,1637.69) 1421.81,1658.16 1385.62,1694.36 1385.62,1847.63 1444.49,1906.5 1482.75,1906.5 1532.51,1956.26 v1(1532.51,1965.39)
  L4 w35: v1(1273,427.5) 1273,1120.39 1216.53,1176.86 1216.53,1432.41 v1(1421.81,1637.69)
  BOTTOM w35: R130.1@1421.81,1598.71 v1(1421.81,1637.69) ; v1(1532.51,1965.39) 1532.51,2023.9 1573.69,2065.07 1602.85,2065.07 1622.17,2084.39 1622.17,2129.42 1722.23,2229.48 J4.3@1827.5,2229.48
  BOTTOM w40: J5.1@527.5,298.28 527.5,354.21 555.79,382.5 v1(713,382.5)
MCU_5V: J5.2 J7.3 R115.1 | length 113.2
  BOTTOM w40: v1(491,567) 491,565 527.5,528.5 J5.2@527.5,520.72 554.72,493.5 v1(568,493.5)
  other v1: 1842,375.5 1795,377.5 1785,412.5 1789,449.5 563.35,563.88 442,566
MCU_SOP0: R36.1 R93.2 | length 1827.4
  TOP w4: R93.2@981.12,662.25 981.37,662.5 1008.07,662.5 1018.07,672.5 v1(1042,672.5) ; v1(1388,1955.5) 1419.02,1955.5 R36.1@1427.25,1963.73
  L4 w4: v1(1042,672.5) 1014.76,672.5 833.27,853.99 833.27,1266 900.06,1332.79 986.37,1332.79 1136.19,1482.61 1136.19,1545.85 1170.68,1580.34 1233.92,1580.34 1408.36,1754.78 1408.36,1905.15 1388,1925.51 v1(1388,1955.5)
MCU_SOP1: R35.1 R112.2 | length 2227.8
  TOP w4: R112.2@649.32,428.65 670.8,450.13 670.8,493.87 758.43,581.5 900,581.5 v1(945,626.5) ; v1(1289.22,1963.5) 1292,1963.5 1292,1963.73 R35.1@1326.75,1963.73
  L4 w4: v1(945,626.5) 945,716.46 816,845.47 816,1274.25 893.21,1351.46 985.52,1351.46 1119.57,1485.51 1119.57,1548.37 1172.95,1601.74 1235.8,1601.74 1392.87,1758.81 1392.87,1900.12 1329.49,1963.5 v1(1289.22,1963.5)
MCU_SOP2: R32.1 R101.2 | length 2508.4
  TOP w4: R101.2@366.98,527.75 354,540.73 354,692.56 380.94,719.5 639.5,719.5 735.44,623.56 894.06,623.56 v1(907,636.5) ; v1(1230.88,2082.91) 1230.88,2109.43 1264.17,2142.71 R32.1@1277.55,2142.71
  BOTTOM w4: v1(907,636.5) 1203.06,932.56 1203.06,1086.07 1212.27,1095.28 1212.27,1246.27 1197.8,1260.74 1197.8,1344.98 1177.01,1365.77 1177.01,1579.55 1138.11,1618.45 1138.11,1836.5 1194,1892.39 1194,2046.03 v1(1230.88,2082.91)
MISO1: R3.2 R6.2 R63.2 U13.1 | length 2110.7
  TOP w4: v1(1091.14,2184) 1091.14,2228.49 R3.2@1092.38,2229.73 R6.2@1129,2229.73 R63.2@1161.25,2229.73 ; U13.1@1115.48,1236.74 1115.48,1244.11 1123.45,1252.09 1132.13,1252.09 v1(1142.7,1262.66)
  L4 w4: v1(849.41,1856.45) 862.04,1869.07 1119.61,1869.07 1132.48,1881.93 1132.48,1926.55 1119.53,1939.5 847.66,1939.5 838.72,1948.44 838.72,1973.28 853.87,1988.44 1122.42,1988.44 1132.73,1998.74 1132.73,2027.07 1111.24,2048.56 1111.24,2163.9 v1(1091.14,2184)
  BOTTOM w4: v1(849.41,1856.45) 849.41,1839.21 892.76,1795.86 892.76,1653.82 944.64,1601.94 1055.82,1601.94 1108.12,1549.65 1108.12,1322.45 1142.7,1287.87 v1(1142.7,1262.66)
MOSI1: R4.2 R5.2 R28.1 U13.4 | length 1674
  TOP w4: R28.1@899.11,2142.71 v1(922.14,2142.71) 922.14,2192.44 945.32,2215.62 945.32,2263.64 954.97,2273.3 999.97,2273.3 1007.28,2265.99 1007.28,2243.76 1021.31,2229.73 R4.2@1022.55,2229.73 R5.2@1054.91,2229.73 ; U13.4@1068.23,1238.71 1068.23,1247.88 1071.32,1250.96 v1(1071.32,1265.52)
  L4 w4: v1(798.81,1837.82) 773.47,1863.16 773.47,1982.23 842.5,2051.26 842.5,2099.35 885.87,2142.71 v1(922.14,2142.71)
  BOTTOM w4: v1(798.81,1837.82) 861.02,1775.61 861.02,1636.32 946.32,1551.02 1070.11,1551.02 1088.84,1532.29 1088.84,1431 1082.36,1424.52 1040.85,1424.52 1034.78,1418.45 1034.78,1400.99 1041.07,1394.69 1088.48,1394.69 1090.12,1393.06 1090.12,1372.79 1088.06,1370.72 1036.97,1370.72 1032.95,1366.7 1032.95,1345.67 1037.05,1341.57 1067.16,1341.57 1071.32,1337.41 v1(1071.32,1265.52)
NetC1_2: C1.2 C2.2 R37.2 U1.8 | length 181.5
  TOP w15: U1.8@1957.43,2055.68 1959.01,2055.68 1992.32,2088.99 C1.2@2023.97,2088.99
  TOP w20: R37.2@2011.24,2037.7 R37.2@2012.81,2039.27 ; C2.2@2011.48,1995.26 2012.81,1996.59 R37.2@2012.81,2039.27 ; C1.2@2023.97,2088.99 2023.97,2080.44 2012.81,2069.28 R37.2@2012.81,2039.27
NetC16_2: C16.2 R78.1 U3.3 | length 73.3
  TOP w20: U3.3@1092.01,1043.91 C16.2@1092.01,1117.17
NetC18_2: C18.2 R81.2 R82.1 U4.3 | length 165.1
  TOP w12: C18.2@2028.37,1034.87 2035.38,1027.86 U4.3@2035.38,968.04
  TOP w15: R81.2@2008.79,1085.17 2046.37,1085.17 2046.41,1085.13 2046.41,1061.41 2028.37,1043.37 C18.2@2028.37,1034.87
NetC22_1: C22.1 U4.6 | length 96.1
  TOP w12: 2035.38,814.78 U4.6@2035.38,857.8
  TOP w15: C22.1@1989.97,796.17 1990.2,796.4 2017,796.4 2035.38,814.78
NetC24_2: C24.2 R85.1 R87.2 | length 86
  TOP w4: C24.2@1092.37,711.14 R87.2@1092.37,747.12 R85.1@1142.37,747.12
NetC26_1: C26.1 C27.1 D3.1 F1.1 FB1.1 FB2.1
NetC28_1: C28.1 R121.2 R122.1 U5.10 | length 406
  TOP w10: v1(1621.29,1622.33) 1638.72,1639.76 U5.10@1638.72,1653.52
  L4 w10: v1(1621.29,1622.33) 1653.08,1654.13 1653.08,1843.16 1656.89,1846.97 v1(1656.89,1868.87)
  BOTTOM w20: v1(1656.89,1868.87) 1671.7,1883.68 R121.2@1671.7,1893.62 R122.1@1713.14,1893.62 C28.1@1713.14,1927.64
NetC29_2: C29.2 U5.7 | length 68.8
  TOP w10: C29.2@1531.03,1620.25 1557.33,1620.25 1579.66,1642.59 U5.7@1579.66,1653.52
NetC44_2: C44.2 U5.19 | length 31.8
  TOP w4: U5.19@1579.66,1803.12 C44.2@1579.66,1834.93
NetC46_1: C46.1 R131.1 R132.2 U5.16 | length 391.6
  TOP w10: U5.16@1638.72,1803.12 1638.72,1816.88 1643.02,1821.18 v1(1677.15,1821.18)
  L4 w10: v1(1670.47,1623.26) 1683.83,1636.62 1683.83,1792.62 1677.15,1799.3 v1(1677.15,1821.18)
  BOTTOM w20: v1(1670.47,1623.26) R132.2@1670.47,1566.52 C46.1@1708.82,1566.52 R131.1@1708.82,1596.78 ; R131.1@1708.82,1601.78 R131.1@1708.82,1596.78 ; R131.1@1709.84,1596.78 R131.1@1708.82,1596.78
NetC71_2: C71.2 R154.1 U6.96 | length 171.8
  TOP w20: R154.1@736,946.4 736,975.5 v1(751,990.5) 771,1010.5 C71.2@794.7,1010.5
  BOTTOM w8: v1(751,990.5) 764.45,1003.95 U6.96@814.94,1003.95
NetC78_1: C78.1 R156.1 R157.2 U9.5 | length 394
  TOP w20: v1(63,906.5) 63,822.5 120.71,764.79 120.71,690.79 v1(125,686.5)
  BOTTOM w12: U9.5@101.22,673.32 111.82,673.32 v1(125,686.5)
  BOTTOM w20: v1(63,906.5) 64,906.5 67.1,903.4 C78.1@67.1,878.84 C78.1@67.1,878.45 ; v1(125,686.5) R156.1@158.03,719.51 158.03,720.29 198.86,720.29 R157.2@199.2,719.95
NetC79_2: C79.2 C80.2 R176.1 U9.1 U9.2 | length 197.5
  TOP w30: v1(-32,807.5) -32,803.5 -4,775.5 R176.1@-4,775
  BOTTOM w12: C79.2@24.44,838.37 U9.1@24.45,791.44 U9.2@50.04,791.44
  BOTTOM w15: C79.2@24.44,838.37 25.27,839.2 C79.2@25.62,839.55
  BOTTOM w20: -32,822.6 -15.4,839.2 C79.2@25.27,839.2
  BOTTOM w25: v1(-32,807.5) -32,822.6
NetC84_2: C84.2 R183.1 U11.5 | length 81.1
  TOP w12: U11.5@1680.59,1024.75 1718.82,1024.75 R183.1@1720.75,1026.68
  TOP w20: C84.2@1720.05,1066.5 1720.05,1027.38 R183.1@1720.75,1026.68
NetC85_1: C85.1 R187.1 U12.5 | length 80.4
  TOP w10: R187.1@200.81,930.06 R187.1@200.81,932.42 ; U12.5@200.81,970.05 R187.1@200.81,932.42 ; R187.1@200.98,932.25 R187.1@200.81,932.42
  TOP w20: R187.1@200.98,933.03 C85.1@241.11,933.03
NetC86_2: C86.2 R190.1 | length 59.3
  TOP w19: C86.2@1402.01,1265.35 1403.85,1263.51 v1(1403.85,1230.46)
  BOTTOM w20: v1(1403.85,1230.46) R190.1@1403.85,1254.06
NetC87_2: C87.2 R191.1 | length 48.8
  TOP w19.68: C87.2@1735,1249.96 v1(1758.87,1249.97)
  BOTTOM w19.68: R191.1@1734.8,1247.97 1736.8,1249.97 v1(1758.87,1249.97)
NetC88_2: C88.2 R192.1 | length 64.3
  TOP w22: v1(1363,918) 1364.7,916.3 C88.2@1364.7,886.95
  BOTTOM w22: v1(1363,918) 1364.9,916.1 R192.1@1364.9,886.25
NetC89_2: C89.2 R193.1 | length 48.5
  TOP w22: C89.2@1735.22,885.04 v1(1759.28,885.04)
  BOTTOM w19.68: R193.1@1734.82,885.04 v1(1759.28,885.04)
NetD2_1: D2.1 R80.2 | length 56.8
  TOP w15: 10.07,1106.06 D2.1@29.57,1106.06
  TOP w20: R80.2@-27.25,1106.06 10.07,1106.06
NetDS1_1: DS1.1 R90.1 | length 191.9
  TOP w20: DS1.1@119.71,580.63 154.13,580.63 178,604.5 178,696.43 R90.1@200.46,718.89
NetDS2_1: DS2.1 R100.1 | length 56
  TOP w20: DS2.1@234.35,581.16 234.35,537.3 R100.1@242.91,528.74
NetDS3_1: DS3.1 R103.1 | length 84.2
  TOP w20: DS3.1@17.03,580.31 17.03,551.47 26.47,542.03 R103.1@26.47,500.07
NetDS3_2: DS3.2 Q1.3 | length 175.9
  TOP w20: DS3.2@17.03,643.31 30.19,643.31 67,606.5 67,571.61 Q1.3@120.58,518.03
NetDS4_1: DS4.1 R117.1 | length 55.7
  TOP w20: DS4.1@255.6,378.87 277.31,378.87 283.72,372.47 R117.1@308.61,372.47
NetDS4_2: DS4.2 Q2.3 | length 183.7
  TOP w20: v1@136,476.5 164.99,476.5 205.53,435.96 DS4.2@255.6,435.96
  BOTTOM w20: Q2.3@120.62,519.41 120.62,493.84 v1(136,478.46)
NetDS5_1: DS5.1 R189.1 | length 47.8
  TOP w4: R189.1@-14.4,247.04 DS5.1@33.45,247.04
NetF1_2: F1.2 P6.1
NetJ1_1: J1.1 J1.2 J1.3 R34.1
NetJ1_4: J1.4 R67.1 | length 169.2
  TOP w4: J1.4@1079.8,1773.27 1079.8,1732.79 1127,1685.59 1127,1627.46 R67.1@1124.25,1624.71
NetJ1_5: J1.5 R29.2 | length 242.4
  TOP w4: v1(961,2092.7) 961,2091.5 962,2091.5 962,2114.9 R29.2@963.83,2116.73 ; J1.5@1060.11,1999.06 1060.95,1999.89 1060.95,2050.59 v1(1075.61,2065.26)
  BOTTOM w4: v1(961,2092.7) 963.2,2092.7 982,2111.5 1029.38,2111.5 v1(1075.61,2065.26)
NetJ1_6: J1.6 R66.1 | length 170.3
  TOP w4: J1.6@1060.11,1773.27 1060.11,1732.53 1077.2,1715.44 1077.2,1682.58 1066.8,1672.18 1066.8,1651.69 1091.75,1626.74 R66.1@1091.75,1624.71
NetJ1_7: J1.7 R17.2 | length 128.4
  TOP w4: J1.7@1040.43,1999.06 1040.43,2040.3 1052.95,2052.82 1052.95,2085.94 1062.09,2095.09 1062.09,2115.88 R17.2@1060.25,2117.73
NetJ1_8: J1.8 R65.1 | length 165
  TOP w4: J1.8@1040.43,1773.27 1040.43,1732.78 1066.2,1707.01 1066.2,1687.13 1055.8,1676.73 1055.8,1628.16 R65.1@1059.25,1624.71
NetJ1_9: J1.9 R75.2 | length 1738.7
  TOP w4: v1(996,1919.5) 1020.74,1944.24 J1.9@1020.74,1999.25
  L4 w4: v1(868.61,1263.6) 918.85,1313.84 1000.19,1313.84 1156.91,1470.56 v1(1156.91,1537.49)
  BOTTOM w4: v1(868.61,1263.6) 894.2,1263.6 R75.2@904.07,1273.47 ; v1@996,1915.83 v1(996,1919.5) 940.68,1919.5 934.68,1913.5 934.68,1898.77 941.74,1891.71 989.38,1891.71 996,1885.09 996,1871.47 992.15,1867.62 938.92,1867.62 931.82,1860.53 931.82,1847.48 939.11,1840.19 990.13,1840.19 996,1834.32 996,1816.97 989.11,1810.08 936.72,1810.08 930.64,1804 930.64,1791.67 936.41,1785.9 1019.92,1785.9 1026.66,1779.16 1026.66,1764.48 1021.96,1759.77 1001.52,1759.77 995.57,1753.83 995.57,1705.34 1026.86,1674.05 1059.61,1674.05 1076.47,1690.91 1076.47,1801.48 1091.61,1816.61 1116.68,1816.61 1123.37,1809.92 1123.37,1610.66 1156.91,1577.12 v1(1156.91,1537.49)
NetJ1_10: J1.10 R64.1 | length 151
  TOP w4: J1.10@1020.74,1773.27 1020.74,1630.58 R64.1@1026.61,1624.71
NetJ1_11: J1.11 R28.2 | length 860.2
  TOP w4: R28.2@899.11,2116.73 899.11,2088.93 913.83,2074.21 938.09,2074.21 941.03,2077.15 941.03,2114.93 944.66,2118.56 944.66,2156.01 947.43,2158.77 955.82,2158.77 958.11,2161.06 958.11,2168.58 954.7,2171.99 933.94,2171.99 930.49,2175.44 930.49,2186.53 933.99,2190.03 984.74,2190.03 988.19,2193.48 988.19,2200.94 983.84,2205.29 956.7,2205.29 953.32,2208.67 953.32,2259.3 957.93,2263.91 963.56,2263.91 967.29,2260.18 967.29,2223.67 970.61,2220.36 976.06,2220.36 980.15,2224.45 980.15,2262.52 982.93,2265.3 995.63,2265.3 999.28,2261.65 999.28,2219.77 1005.6,2213.45 1041.87,2213.45 1043.72,2211.61 1043.72,2201.03 1040.23,2197.54 1009.55,2197.54 1004.18,2192.17 1004.18,2164.48 1012.11,2156.55 1012.11,2105.06 1020.91,2096.27 1020.91,2081.65 1001.06,2061.8 J1.11@1001.06,1999.06
NetJ1_12: J1.12 R63.1 | length 606
  TOP w4: J1.12@1001.08,1773.43 1001.08,1813.44 1005.86,1818.22 1005.86,1824.49 v1(1024.02,1842.66) ; R63.1@1161.27,2255.87 1168.02,2262.62 v1(1168.02,2281.66)
  BOTTOM w4: v1(1024.02,1842.66) 1024.02,1900.87 1097.38,1974.23 1097.38,2103.43 1168.02,2174.07 v1(1168.02,2281.66)
NetJ1_13: J1.13 R27.2 | length 200.2
  TOP w10: 961.63,2058 971,2058 981.37,2047.63 J1.13@981.37,1999.25
  TOP w15: R27.2@866.61,2116.73 866.61,2102.26 910.87,2058 961.63,2058
NetJ1_14: J1.14 R7.1 | length 164.4
  TOP w4: R7.1@962.11,1624.9 962.11,1626.9 990.89,1655.68 990.89,1722.39 981.37,1731.92 J1.14@981.37,1773.46
NetJ1_16: J1.16 R62.1 | length 162
  TOP w4: R62.1@929.85,1624.71 929.85,1631.34 949,1650.49 949,1694.5 962,1707.5 962,1772.96 J1.16@961.69,1773.27
NetJ1_51: J1.51 R23.2 | length 126.5
  TOP w4: R23.2@585.61,2116.73 589.2,2113.14 589.2,2074.3 607,2056.5 607,1999.61 J1.51@607.36,1999.25
NetJ1_53: J1.53 R22.2 | length 141.6
  TOP w4: R22.2@550.11,2116.73 550.11,2075.38 568.99,2056.5 583.67,2056.5 587.67,2052.5 J1.53@587.67,1999.25
NetJ1_55: J1.55 R33.2 | length 138
  TOP w4: R33.2@517.39,2116.29 542,2091.68 542,2070.5 567.99,2044.51 J1.55@567.99,1999.25
NetJ1_57: J1.57 R21.2 | length 161.4
  TOP w4: R21.2@484.35,2116.73 484.35,2075.36 496.36,2063.35 525.81,2063.35 548.3,2040.86 J1.57@548.3,1999.06
NetJ1_59: J1.59 R20.2 | length 162.1
  TOP w4: R20.2@452.11,2116.73 466.46,2102.38 466.46,2077.51 490.86,2053.11 512.6,2053.11 528.62,2037.1 J1.59@528.62,1999.06
NetJ2_1: J2.1 R111.2 | length 89.3
  TOP w7.08: J2.1@2158.71,353.76 R111.2@2158.71,443.03
NetJ3_1: J3.1 R85.2 U3.7 | length 1393.2
  TOP w4: v1(1129,592) 1129,654.01 1163.94,688.95 1163.94,764.77 1142.01,786.7 U3.7@1142.01,835.25
  BOTTOM w4: J3.1@532.8,-21.34 596.43,-84.97 815.88,-84.97 1069,168.15 1069,422.21 1098.42,451.63 1098.42,579.01 1111.41,592 v1(1129,592)
NetJ3_3: J3.3 R87.1 U3.6 | length 1006.8
  TOP w4: v1(1068,513) 1068,570 1073.27,575.27 1073.27,767.39 1092.01,786.13 U3.6@1092.01,835.25
  BOTTOM w4: J3.3@808.39,-21.34 869.19,39.46 897.63,39.46 1058,199.83 1058,431.43 1087.42,460.85 1087.42,493.58 v1(1068,513)
NetJ5_5: J5.5 R168.2 R169.2 | length 153.8
  BOTTOM w4: R169.2@685.13,182.27 R168.2@719.63,182.27 727.5,190.14 J5.5@727.5,298.28
NetJ5_6: J5.6 R104.1 | length 103.1
  TOP w4: v1(692.2,485.5) 699,485.5 699,486.29 R104.1@727.75,486.29
  BOTTOM w4: v1(692.2,485.5) 721.01,485.5 727.5,491.99 J5.6@727.5,520.72
NetJ5_7: J5.7 R166.2 R167.2 | length 151.3
  BOTTOM w4: R167.2@799.13,182.27 R166.2@831.5,182.27 ; J5.7@827.5,298.28 827.5,186.27 R166.2@831.5,182.27 ; R166.2@832.75,182.27 R166.2@831.5,182.27
NetJ5_8: J5.8 R94.1 | length 79.3
  TOP w4: R94.1@828.25,519.29 836.04,511.5 v1(864,511.5)
  BOTTOM w4: J5.8@827.5,520.72 854.78,520.72 v1(864,511.5)
NetJ5_9: J5.9 R165.2 | length 117.7
  BOTTOM w4: J5.9@927.5,298.28 927.5,187.96 R165.2@932.75,182.71
NetJ5_10: J5.10 R105.1 | length 89.3
  TOP w4: R105.1@929.75,486.29 929.75,460.64 v1(930.68,459.71)
  BOTTOM w4: J5.10@927.5,520.72 927.5,462.89 v1(930.68,459.71)
NetJ5_12: J5.12 R106.1 | length 89
  TOP w4: v1(1030,460) 1030.25,460.25 R106.1@1030.25,486.29
  BOTTOM w4: J5.12@1027.5,520.72 1027.5,487 1031,483.5 1031,461 v1(1030,460)
NetJ5_13: J5.13 R76.2 | length 1404.2
  L4 w5: v1(967.07,1265.25) 952.42,1265.25 909.75,1222.58 909.75,1118.82 930.53,1098.04 930.53,845.41 911.43,826.31 911.43,801.43 1017.38,695.49 1049.22,695.49 1068.06,676.65 1068.06,658.84 996.77,587.55 996.77,357.08 1004.35,349.5 1033.15,349.5 1043.17,359.52 1043.17,385.54 1047.58,389.95 1069.75,389.95 1075.9,383.79 1075.9,358.4 1084.81,349.5 v1(1164,349.5)
  BOTTOM w4: R76.2@941.93,1273.47 950.15,1265.25 v1(967.07,1265.25) ; J5.13@1127.5,298.28 1127.5,322.04 1144.91,339.45 1153.95,339.45 v1(1164,349.5)
NetJ5_14: J5.14 R107.1 | length 104.2
  TOP w20: R107.1@1129.75,480.38 R107.1@1129.75,479.59 1145.51,463.83 v1(1157.35,463.83)
  BOTTOM w20: J5.14@1127.5,520.72 1127.5,493.69 v1(1157.35,463.83)
NetJ5_15: J5.15 R164.2 | length 198.6
  BOTTOM w4: J5.15@1227.5,298.28 1227.5,274.7 1267.77,234.43 1324.34,234.43 1337.16,221.61 1337.16,200.3 R164.2@1352.75,184.71
NetJ5_16: J5.16 R102.1 | length 88.1
  TOP w4: v1(1227.5,460.5) 1230.25,463.25 R102.1@1230.25,487.29
  BOTTOM w4: v1(1227.5,460.5) J5.16@1227.5,520.72
NetJ5_17: J5.17 R163.2 | length 143.2
  BOTTOM w4: J5.17@1327.5,298.28 1327.5,274.03 1359.72,241.8 1365.87,241.8 1390.25,217.42 R163.2@1390.25,184.71
NetJ5_18: J5.18 R108.1 | length 106
  TOP w4: v1(1327.5,451) 1327.5,483.24 R108.1@1330.35,486.09
  BOTTOM w4: v1(1327.5,451) J5.18@1327.5,520.72
NetJ5_19: J5.19 R162.2 | length 130.7
  BOTTOM w4: J5.19@1427.5,298.28 1427.5,275.6 1470.25,232.85 R162.2@1470.25,185.27
NetJ5_20: J5.20 R109.1 | length 129.3
  TOP w4: R109.1@1362.85,486.09 1368,480.94 v1(1368,458)
  BOTTOM w4: v1(1368,458) 1388,458 1427.5,497.5 J5.20@1427.5,520.72
NetJ6_1: J6.1 R19.2 | length 186.1
  TOP w4: R19.2@419.25,2116.73 419.25,2090.25 v1(426,2083.5)
  BOTTOM w4: v1(426,2083.5) 465,2083.5 527.5,2021 J6.1@527.5,1998.28
NetJ6_3: J6.3 R24.2 | length 140.1
  TOP w4: v1(669,2084.5) 679.75,2095.25 R24.2@679.75,2116.73
  BOTTOM w4: J6.3@627.5,1998.28 627.5,2021.01 669,2062.51 v1(669,2084.5)
NetJ6_5: J6.5 R25.2 | length 119
  TOP w4: R25.2@726.25,2116.73 727.5,2115.48 v1(727.5,2081)
  BOTTOM w4: J6.5@727.5,1998.28 v1(727.5,2081)
NetJ6_8: J6.8 R9.1 | length 103.4
  TOP w4: v1(791,2254.5) 829.54,2254.5 R9.1@829.75,2254.71
  BOTTOM w4: v1(791,2254.5) 791,2230.5 800.78,2220.72 J6.8@827.5,2220.72
NetJ6_9: J6.9 R26.2 | length 170.8
  TOP w4: R26.2@834.11,2116.73 834,2116.62 834,2097.16 868.33,2062.83 v1(871,2065.5)
  BOTTOM w4: v1(871,2065.5) 885,2065.5 927.5,2023 J6.9@927.5,1998.28
NetJ6_10: J6.10 R2.1 | length 104.6
  TOP w4: v1(927.5,2290) 927.5,2258.26 R2.1@930.05,2255.71
  BOTTOM w4: J6.10@927.5,2220.72 v1(927.5,2290)
NetJ6_11: J6.11 R18.2 | length 123.1
  TOP w4: R18.2@1028.21,2117.08 1033,2112.29 v1(1033,2063.5)
  BOTTOM w4: J6.11@1027.5,1998.28 1033,2003.78 v1(1033,2063.5)
NetJ6_12: J6.12 R4.1 R5.1 | length 127.6
  TOP w4: v1(1029.55,2283.95) 1029.55,2262.71 R4.1@1022.55,2255.71 R5.1@1054.91,2255.71
  BOTTOM w4: J6.12@1027.5,2220.72 1027.5,2281.9 v1(1029.55,2283.95)
NetJ6_13: J6.13 R31.2 | length 141.8
  TOP w4: v1(1144,2065.5) 1172.22,2093.72 1172.22,2104.9 R31.2@1184,2116.68
  BOTTOM w4: J6.13@1127.5,1998.28 1127.5,2024.01 1144,2040.51 v1(1144,2065.5)
NetJ6_14: J6.14 R3.1 R6.1 | length 230.7
  TOP w4: R3.1@1092.38,2255.71 R6.1@1129,2255.71 1127.41,2257.31 v1(1127.41,2291.34)
  BOTTOM w4: v1(1127.41,2291.34) 1115.57,2303.18 1088.1,2303.18 1082.52,2297.6 1082.52,2272.02 1087.06,2267.48 1104.36,2267.48 1127.5,2244.34 J6.14@1127.5,2220.72
NetJ6_15: J6.15 R32.2 | length 139.2
  TOP w4: v1(1273.57,2083.91) 1273.57,2112.75 R32.2@1277.55,2116.73
  BOTTOM w4: J6.15@1227.5,1998.28 1227.5,2023 1255.37,2050.87 1255.37,2065.71 v1(1273.57,2083.91)
NetJ6_16: J6.16 R10.1 | length 117.2
  TOP w4: R10.1@1239.25,2254.71 1244.82,2260.29 1244.82,2269.29 v1(1256.52,2280.98)
  BOTTOM w4: J6.16@1227.5,2220.72 1227.5,2271.53 1236.95,2280.98 v1(1256.52,2280.98)
NetJ6_17: J6.17 R35.2 | length 79.1
  TOP w4: R35.2@1326.75,1989.71 1328.96,1987.5 v1(1364,1987.5)
  BOTTOM w4: J6.17@1327.5,1998.28 1353.22,1998.28 v1(1364,1987.5)
NetJ6_18: J6.18 R8.1 | length 90.3
  TOP w4: R8.1@1329.55,2255.71 v1(1329.55,2282.95)
  BOTTOM w4: J6.18@1327.5,2220.72 1327.5,2280.9 v1(1329.55,2282.95)
NetJ6_19: J6.19 R36.2 | length 82
  TOP w4: R36.2@1427.25,1989.71 1442.04,2004.5 v1(1464,2004.5)
  BOTTOM w4: J6.19@1427.5,1998.28 1433.72,2004.5 v1(1464,2004.5)
NetJ8_1: J8.1 R161.1 | length 251.7
  BOTTOM w10: J8.1@1996,1.06 J8.1@1996.19,0.88
  BOTTOM w15: J8.1@1996,1.06 1996,162 R161.1@2060,226
NetJ8_5: J8.5 R175.2 | length 302.5
  BOTTOM w15: J8.5@1893.64,0.7 J8.5@1893.82,0.88 1893.82,43.82
  BOTTOM w20: R175.2@1670.82,91.82 1873.82,91.82 1893.82,71.82 1893.82,43.82
NetJ8_6: J8.6 J8.9 J8.10 J8.11 R174.2 U10.5 | length 1021.6
  TOP w10: U10.5@1976,343.69 1976,336.07 1993.21,318.86 1993.21,304.71
  TOP w20: J8.10@1846.58,0.88 1846.57,129.07 1993.21,275.71 1993.21,304.71
  TOP w30: J8.10@1846.58,0.88 J8.11@2043.43,0.88
  BOTTOM w20: J8.11@2043.43,0.88 R174.2@2212.31,0.88
  BOTTOM w30: J8.9@1807.21,-105.42 1807.21,-38.49 J8.10@1846.58,0.88 ; J8.11@2043.43,0.88 2082.8,-38.49 J8.6@2082.8,-105.42
NetP2_1: P2.1 R95.2 | length 141.4
  TOP w4: P2.1@612.44,669.75 648.82,633.37 R95.2@648.82,543.45
NetP3_1: P3.1 R99.2 | length 151.6
  TOP w4: P3.1@409,669.42 397,657.42 397,540.67 R99.2@409.62,528.05
NetP4_1: P4.1 R92.2 | length 125.2
  TOP w4: P4.1@818.44,668.75 824.94,662.25 R92.2@940.92,662.25
NetQ1_1: Q1.1 R116.2 | length 61.1
  TOP w20: R116.2@26.68,416.33 72.04,416.33 Q1.1@83.18,427.47
NetQ2_1: Q2.1 R160.2 | length 195
  BOTTOM w20: R160.2@26.6,415.91 26.6,385.9 40.75,371.75 111.25,371.75 158.02,418.52 Q2.1@158.02,426.89
NetR11_2: R11.2 U3.1 | length 337.7
  TOP w4: U3.1@1192.37,1043.6 1192.37,1057.58 1283.93,1149.14 1283.93,1263.41 1268.75,1278.59 1230.72,1278.59 R11.2@1216.28,1264.15
NetR12_2: R12.2 U3.4 | length 65.8
  TOP w4: R12.2@1015.51,1098.31 1042.37,1071.45 U3.4@1042.37,1043.6
NetR39_2: R39.2 U1.2 | length 62.7
  TOP w4: R39.2@1677.77,1992.45 1691,2005.68 U1.2@1734.99,2005.68
NetR40_1: R40.1 U1.7 | length 147.1
  TOP w4: U1.7@1955.47,2005.68 1967.86,2005.68 2009.79,1963.75 R40.1@2009.79,1888.35
NetR42_2: R42.2 U1.3 | length 57.7
  TOP w4: R42.2@1677.77,1956.85 1678.94,1955.68 U1.3@1734.99,1955.68
NetR44_1: R44.1 U1.6 | length 132.6
  TOP w4: U1.6@1955.47,1955.68 1969.52,1955.68 1993.02,1932.18 1993.02,1870.62 R44.1@2009.79,1853.85
NetR45_1: R45.1 U1.5 | length 120.4
  TOP w4: U1.5@1957.43,1905.68 1957.43,1860.71 R45.1@2010.79,1807.35
NetR68_1: R68.1 SW1.4 | length 69.3
  TOP w15: R68.1@246.04,1534.25 255.94,1524.35 SW1.4@255.94,1469.02
NetR72_1: R72.1 R73.2 SW1.2 | length 104.1
  TOP w15: R73.2@192.05,1409.82 192.5,1410.27 R72.1@192.5,1448.26
  TOP w20: R73.2@192.05,1409.82 194.25,1407.62 206,1407.62 207.6,1406.02 SW1.2@255.94,1406.02
NetR79_2: R79.2 SW2.2 | length 84.3
  TOP w15: SW2.2@254.64,1178.26 260,1172.9 260,1105.29 R79.2@266.45,1098.84
NetR86_1: R86.1 R177.1 R178.2 U3.8 | length 210.1
  TOP w4: U3.8@1192.37,836.91 R86.1@1192.37,786.49 R178.2@1246.5,786.49 1246.5,733.25 R177.1@1209.5,696.25
NetR88_2: R88.2 R89.2 R92.1 R93.1 | length 120.8
  TOP w4: R88.2@941.42,740.25 940.92,739.75 R92.1@940.92,700.84 940.92,700.05 R93.1@981.12,700.05 981.12,739.19 R89.2@981.88,739.95
NetR95_1: R95.1 R96.2 R112.1 R113.2 | length 118.5
  TOP w4: R113.2@608.92,466.45 608.78,466.59 608.78,505.35 648.52,505.35 648.82,505.65 648.82,466.95 R112.1@649.32,466.45
NetR98_2: R98.2 R99.1 R101.1 R114.2 | length 137.9
  TOP w4: R98.2@325.82,528.05 327.44,528.05 365.54,489.95 366.98,489.95 367.28,490.25 409.62,490.25 409.62,452.15 R114.2@409.52,452.05
NetR123_1: R123.1 U6.63 | length 69.2
  BOTTOM w4: U6.63@740.14,1551.19 740.14,1596.11 R123.1@757.28,1613.25
NetR124_1: R124.1 U6.61 | length 504.9
  BOTTOM w4: R124.1@637.72,1650.75 637.72,1671.22 675.02,1708.52 768.8,1708.52 809,1668.32 809,1536.5 794,1521.5 775,1521.5 764,1510.5 713,1510.5 709,1514.5 709,1550.83 U6.61@708.64,1551.19
NetR125_1: R125.1 S1.2 U13.15 | length 504.1
  TOP w4: v1(869.19,1230) S1.2@910,1230 ; U13.15@1139.1,1215.08 1140.97,1216.96 1153.7,1216.96 1159.2,1222.46 1170.65,1222.46 v1@1179.8,1231.61 ; v1(1181.07,1231.61) 1207.07,1231.61 R125.1@1209.58,1234.12
  L4 w4: v1(869.19,1230) 892.6,1230 960.04,1297.45 1147.8,1297.45 1181.07,1264.17 v1(1181.07,1231.61)
NetR126_1: R126.1 U6.62 | length 64.8
  BOTTOM w6: R126.1@717.68,1613.25 724.39,1606.54 U6.62@724.39,1551.19
NetR127_1: R127.1 U6.60 | length 666.9
  BOTTOM w8: 692.89,1508.61 U6.60@692.89,1551.19
  BOTTOM w10: R127.1@598.12,1650.75 606,1658.63 606,1704.43 643.95,1742.38 754.73,1742.38 825.8,1671.31 825.8,1518.3 814,1506.5 782,1506.5 769,1493.5 708,1493.5 692.89,1508.61
NetR128_2: R128.2 U6.33 | length 67.5
  BOTTOM w4: R128.2@246.5,1609.95 267.7,1588.75 U6.33@267.7,1551.19
NetR129_2: R129.2 U6.34 | length 59.9
  BOTTOM w4: U6.34@283.44,1551.19 283.44,1606.04 R129.2@287,1609.6
NetR143_1: R143.1 U8.16 | length 165
  BOTTOM w10: U8.16@1625.81,1110.02 1637.53,1110.03 1643,1115.5 1671,1115.5 1679.82,1124.32
  BOTTOM w20: 1679.82,1124.32 1725.27,1124.32 R143.1@1767.45,1166.5
NetR144_2: R144.2 U8.5 | length 108.5
  BOTTOM w4: R144.2@1381.77,1066.69 1404.08,1089 1427,1089 1433.49,1095.49 1462.92,1095.49 1468.07,1090.34 U8.5@1476.2,1090.34
NetR146_1: R146.1 U8.6 | length 98.9
  BOTTOM w4: R146.1@1381.77,1099.19 1423.19,1099.19 1427.83,1103.83 1461.94,1103.83 1468.13,1110.03 U8.6@1476.2,1110.02
NetR147_1: R147.1 U8.19 | length 139
  BOTTOM w10: U8.19@1625.81,1050.97 1680.53,1050.97
  BOTTOM w20: R147.1@1746.6,1036 R147.1@1755.1,1027.5
  BOTTOM w25: 1680.53,1050.97 1695.5,1036 R147.1@1746.6,1036
NetR152_1: R152.1 U6.95 | length 104
  TOP w20: v1(764,1039.5) 795.1,1070.6 R152.1@795.1,1071.5
  BOTTOM w8: v1(764,1039.5) 783.81,1019.69 U6.95@814.94,1019.69
NetR179_1: R179.1 U11.3 | length 43.1
  TOP w4: R179.1@1581.25,1009.92 1586.11,1005.06 U11.3@1622.33,1005.07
